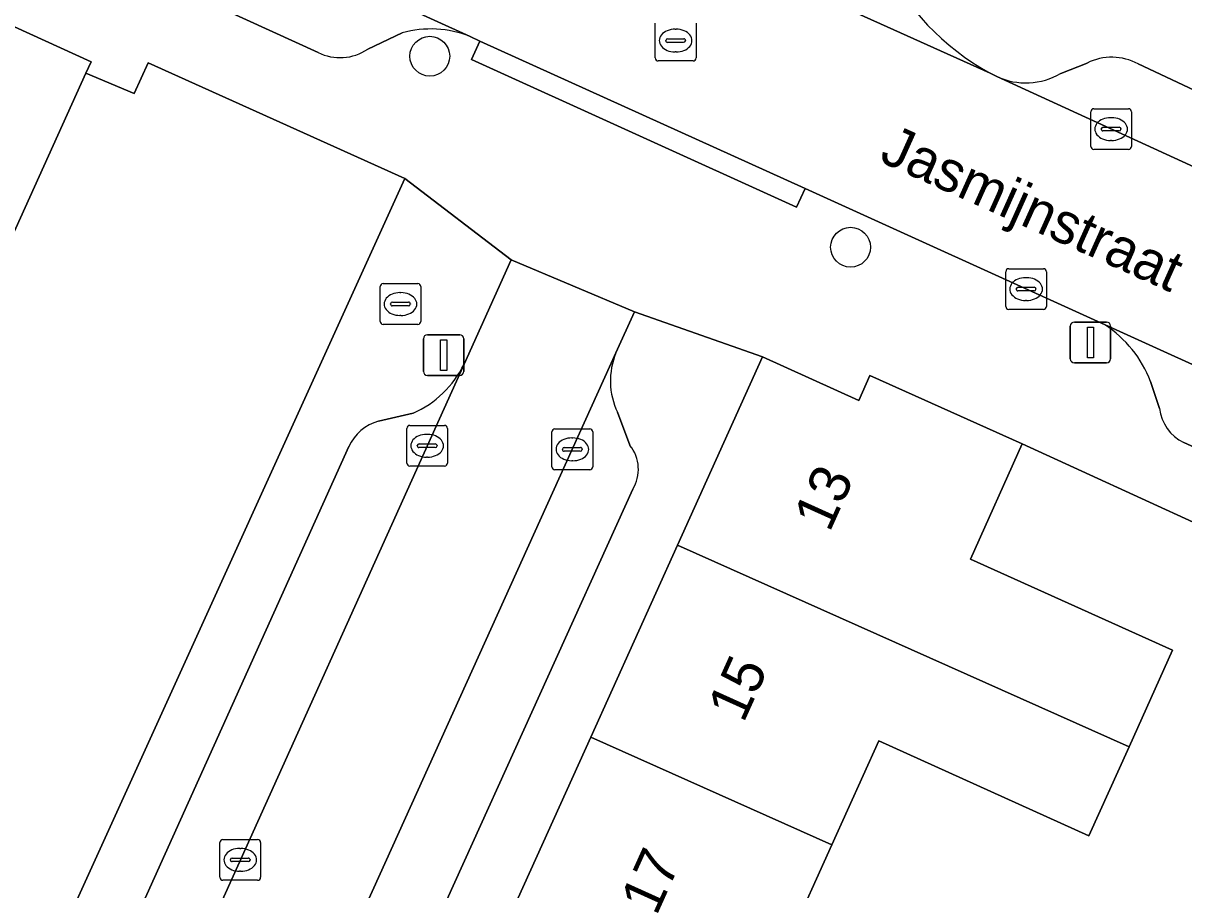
# Model space of a CAD drawing. Extents: x 161838 to 162344, y 381620 to 382160.
# Drawn here: x 162080.38 to 162108.87, y 381769.35 to 381790.62 of the extents above; entities that cross this region are included whole.
import ezdxf

# ---------------------------------------------------------------- set-up
doc = ezdxf.new("R2010")
doc.units = 0
for name, color, linetype in [('IMGEO_Boom', 7, 'Continuous'), ('IMGEO_Brandkraan', 7, 'Continuous'), ('IMGEO_Erf', 7, 'Continuous'), ('IMGEO_Kolk', 7, 'Continuous'), ('IMGEO_Lichtmast', 7, 'Continuous'), ('IMGEO_Muur', 7, 'Continuous'), ('IMGEO_Openbare_ruimte_label', 7, 'Continuous'), ('IMGEO_Pand', 7, 'Continuous'), ('IMGEO_Pand_nummerreeks', 7, 'Continuous'), ('IMGEO_Parkeervlak_open', 7, 'Continuous'), ('IMGEO_Rijbaan_lokaal_open', 7, 'Continuous'), ('IMGEO_Rioolput', 7, 'Continuous'), ('IMGEO_Voetpad_open', 7, 'Continuous')]:
    doc.layers.add(name, color=color, linetype=linetype)

msp = doc.modelspace()

# ---------------------------------------------------------------- linework, layer by layer
at = {"layer": 'IMGEO_Boom'}
for centre in [(162090.359, 381789.808), (162100.687, 381785.121)]:
    msp.add_circle(centre, 0.489, dxfattribs=at)
at = {"layer": 'IMGEO_Brandkraan'}
for p, q in [((162089.138, 381783.301), (162089.138, 381784.153)), ((162089.213, 381784.227), (162090.065, 381784.227)), ((162090.139, 381784.153), (162090.139, 381783.301)), ((162089.626, 381784.007), (162089.651, 381784.007)), ((162089.397, 381783.721), (162089.397, 381783.733)), ((162089.835, 381783.684), (162089.437, 381783.684)), ((162089.44, 381783.77), (162089.838, 381783.77)), ((162089.881, 381783.733), (162089.881, 381783.721)), ((162089.649, 381783.447), (162089.624, 381783.447)), ((162090.065, 381783.227), (162089.213, 381783.227))]:
    msp.add_line(p, q, dxfattribs=at)
for points in [[(162089.138, 381783.301), (162089.138, 381784.153)], [(162089.213, 381784.227), (162090.065, 381784.227)], [(162090.139, 381784.153), (162090.139, 381783.301)], [(162090.065, 381783.227), (162089.213, 381783.227)]]:
    msp.add_lwpolyline(points, dxfattribs=at)
for centre, radius, start, end in [((162089.215, 381784.151), 0.0765, 91.552, 178.448), ((162089.215, 381784.151), 0.0765, 91.552, 178.448), ((162090.063, 381784.151), 0.0765, 1.552, 88.448), ((162090.063, 381784.151), 0.0765, 1.552, 88.448), ((162089.437, 381783.73), 0.0403, 85.8775, 175.7526), ((162089.434, 381783.72), 0.0366, 178.938, 274.7102), ((162089.838, 381783.727), 0.043, 264.8664, 352.4533), ((162089.842, 381783.732), 0.0386, 1.7309, 96.639), ((162089.215, 381783.303), 0.0765, 181.552, 268.448), ((162089.215, 381783.303), 0.0765, 181.552, 268.448), ((162090.063, 381783.303), 0.0765, 271.552, 358.448), ((162090.063, 381783.303), 0.0765, 271.552, 358.448)]:
    msp.add_arc(centre, radius, start, end, dxfattribs=at)
for centre, major_axis, ratio, start_param, end_param in [((162089.625, 381783.727), (-0.387, 0.002), 0.722429, 4.712389, 7.853982), ((162089.65, 381783.727), (-0.39, 0.002), 0.717154, 1.570796, 4.712389)]:
    msp.add_ellipse(centre, major_axis=major_axis, ratio=ratio, start_param=start_param, end_param=end_param, dxfattribs=at)
at = {"layer": 'IMGEO_Erf'}
msp.add_lwpolyline([(162068.579, 381756.936), (162068.219, 381756.057), (162074.49, 381753.282), (162089.747, 381786.804), (162083.445, 381789.649), (162083.105, 381788.89), (162081.916, 381789.39), (162079.965, 381785.079), (162077.918, 381780.552), (162075.797, 381775.863), (162073.603, 381771.013), (162071.478, 381766.316), (162069.301, 381761.504), (162067.446, 381757.401)], close=True, dxfattribs=at)
msp.add_lwpolyline([(162119.551, 381773.591), (162104.902, 381780.293), (162103.63, 381777.467), (162108.591, 381775.234), (162107.525, 381772.865), (162106.539, 381770.675), (162101.379, 381773.006), (162100.229, 381770.46), (162099.172, 381768.121), (162104.172, 381765.858), (162103.149, 381763.595), (162102.061, 381761.187), (162097.027, 381763.433), (162095.939, 381761.023), (162094.867, 381758.649), (162099.869, 381756.389), (162098.796, 381754.013), (162097.756, 381751.711), (162092.728, 381753.983), (162091.62, 381751.529), (162090.929, 381750), (162090.511, 381749.074), (162095.561, 381746.795)], dxfattribs=at)
at = {"layer": 'IMGEO_Kolk'}
for p, q in [((162106.584, 381787.594), (162106.584, 381788.446)), ((162106.659, 381788.52), (162107.511, 381788.52)), ((162107.585, 381788.446), (162107.585, 381787.594)), ((162107.072, 381788.3), (162107.097, 381788.3)), ((162106.843, 381788.014), (162106.843, 381788.026)), ((162107.281, 381787.977), (162106.883, 381787.977)), ((162106.886, 381788.063), (162107.284, 381788.063)), ((162107.327, 381788.026), (162107.327, 381788.014)), ((162107.511, 381787.52), (162106.659, 381787.52)), ((162107.095, 381787.74), (162107.07, 381787.74)), ((162104.497, 381783.668), (162104.497, 381784.52)), ((162104.572, 381784.594), (162105.424, 381784.594)), ((162105.498, 381784.52), (162105.498, 381783.668)), ((162104.756, 381784.088), (162104.756, 381784.1)), ((162104.799, 381784.137), (162105.197, 381784.137)), ((162104.985, 381784.374), (162105.01, 381784.374)), ((162105.24, 381784.1), (162105.24, 381784.088)), ((162105.194, 381784.051), (162104.796, 381784.051)), ((162105.008, 381783.814), (162104.983, 381783.814)), ((162105.424, 381783.594), (162104.572, 381783.594)), ((162089.868, 381780.75), (162090.72, 381780.75)), ((162089.793, 381779.824), (162089.793, 381780.676)), ((162090.281, 381780.53), (162090.306, 381780.53)), ((162090.794, 381780.676), (162090.794, 381779.824)), ((162093.357, 381779.736), (162093.357, 381780.588)), ((162093.432, 381780.662), (162094.284, 381780.662)), ((162093.845, 381780.442), (162093.87, 381780.442)), ((162094.358, 381780.588), (162094.358, 381779.736)), ((162090.052, 381780.244), (162090.052, 381780.256)), ((162090.49, 381780.207), (162090.092, 381780.207)), ((162090.095, 381780.293), (162090.493, 381780.293)), ((162090.536, 381780.256), (162090.536, 381780.244)), ((162093.616, 381780.156), (162093.616, 381780.168)), ((162094.054, 381780.119), (162093.656, 381780.119)), ((162093.659, 381780.205), (162094.057, 381780.205)), ((162094.1, 381780.168), (162094.1, 381780.156)), ((162090.304, 381779.97), (162090.279, 381779.97)), ((162093.868, 381779.882), (162093.843, 381779.882)), ((162090.72, 381779.75), (162089.868, 381779.75)), ((162094.284, 381779.662), (162093.432, 381779.662)), ((162085.204, 381769.662), (162085.204, 381770.514)), ((162085.279, 381770.588), (162086.131, 381770.588)), ((162086.205, 381770.514), (162086.205, 381769.662)), ((162085.692, 381770.368), (162085.717, 381770.368)), ((162085.463, 381770.082), (162085.463, 381770.094)), ((162085.901, 381770.045), (162085.503, 381770.045)), ((162085.506, 381770.131), (162085.904, 381770.131)), ((162085.947, 381770.094), (162085.947, 381770.082)), ((162086.131, 381769.588), (162085.279, 381769.588)), ((162085.715, 381769.808), (162085.69, 381769.808))]:
    msp.add_line(p, q, dxfattribs=at)
for points in [[(162106.584, 381787.594), (162106.584, 381788.446)], [(162106.659, 381788.52), (162107.511, 381788.52)], [(162107.585, 381788.446), (162107.585, 381787.594)], [(162107.511, 381787.52), (162106.659, 381787.52)], [(162104.497, 381783.668), (162104.497, 381784.52)], [(162104.572, 381784.594), (162105.424, 381784.594)], [(162105.498, 381784.52), (162105.498, 381783.668)], [(162105.424, 381783.594), (162104.572, 381783.594)], [(162089.868, 381780.75), (162090.72, 381780.75)], [(162089.793, 381779.824), (162089.793, 381780.676)], [(162090.794, 381780.676), (162090.794, 381779.824)], [(162093.357, 381779.736), (162093.357, 381780.588)], [(162093.432, 381780.662), (162094.284, 381780.662)], [(162094.358, 381780.588), (162094.358, 381779.736)], [(162090.72, 381779.75), (162089.868, 381779.75)], [(162094.284, 381779.662), (162093.432, 381779.662)], [(162085.204, 381769.662), (162085.204, 381770.514)], [(162085.279, 381770.588), (162086.131, 381770.588)], [(162086.205, 381770.514), (162086.205, 381769.662)], [(162086.131, 381769.588), (162085.279, 381769.588)]]:
    msp.add_lwpolyline(points, dxfattribs=at)
for centre, radius, start, end in [((162106.661, 381788.444), 0.0765, 91.552, 178.448), ((162106.661, 381788.444), 0.0765, 91.552, 178.448), ((162107.509, 381788.444), 0.0765, 1.552, 88.448), ((162107.509, 381788.444), 0.0765, 1.552, 88.448), ((162106.883, 381788.023), 0.0403, 85.8775, 175.7526), ((162106.88, 381788.013), 0.0366, 178.938, 274.7102), ((162107.284, 381788.02), 0.043, 264.8664, 352.4533), ((162107.288, 381788.025), 0.0386, 1.7309, 96.639), ((162106.661, 381787.596), 0.0765, 181.552, 268.448), ((162106.661, 381787.596), 0.0765, 181.552, 268.448), ((162107.509, 381787.596), 0.0765, 271.552, 358.448), ((162107.509, 381787.596), 0.0765, 271.552, 358.448), ((162104.574, 381784.518), 0.0765, 91.552, 178.448), ((162104.574, 381784.518), 0.0765, 91.552, 178.448), ((162105.422, 381784.518), 0.0765, 1.552, 88.448), ((162105.422, 381784.518), 0.0765, 1.552, 88.448), ((162104.796, 381784.097), 0.0403, 85.8775, 175.7526), ((162105.201, 381784.099), 0.0386, 1.7309, 96.639), ((162104.793, 381784.087), 0.0366, 178.938, 274.7102), ((162105.197, 381784.094), 0.043, 264.8664, 352.4533), ((162104.574, 381783.67), 0.0765, 181.552, 268.448), ((162104.574, 381783.67), 0.0765, 181.552, 268.448), ((162105.422, 381783.67), 0.0765, 271.552, 358.448), ((162105.422, 381783.67), 0.0765, 271.552, 358.448), ((162089.87, 381780.674), 0.0765, 91.552, 178.448), ((162089.87, 381780.674), 0.0765, 91.552, 178.448), ((162090.718, 381780.674), 0.0765, 1.552, 88.448), ((162090.718, 381780.674), 0.0765, 1.552, 88.448), ((162093.434, 381780.586), 0.0765, 91.552, 178.448), ((162093.434, 381780.586), 0.0765, 91.552, 178.448), ((162094.282, 381780.586), 0.0765, 1.552, 88.448), ((162094.282, 381780.586), 0.0765, 1.552, 88.448), ((162090.092, 381780.253), 0.0403, 85.8775, 175.7526), ((162090.089, 381780.243), 0.0366, 178.938, 274.7102), ((162090.493, 381780.25), 0.043, 264.8664, 352.4533), ((162090.497, 381780.255), 0.0386, 1.7309, 96.639), ((162093.656, 381780.165), 0.0403, 85.8775, 175.7526), ((162093.653, 381780.155), 0.0366, 178.938, 274.7102), ((162094.057, 381780.162), 0.043, 264.8664, 352.4533), ((162094.061, 381780.167), 0.0386, 1.7309, 96.639), ((162089.87, 381779.826), 0.0765, 181.552, 268.448), ((162089.87, 381779.826), 0.0765, 181.552, 268.448), ((162090.718, 381779.826), 0.0765, 271.552, 358.448), ((162090.718, 381779.826), 0.0765, 271.552, 358.448), ((162093.434, 381779.738), 0.0765, 181.552, 268.448), ((162093.434, 381779.738), 0.0765, 181.552, 268.448), ((162094.282, 381779.738), 0.0765, 271.552, 358.448), ((162094.282, 381779.738), 0.0765, 271.552, 358.448), ((162085.281, 381770.512), 0.0765, 91.552, 178.448), ((162085.281, 381770.512), 0.0765, 91.552, 178.448), ((162086.129, 381770.512), 0.0765, 1.552, 88.448), ((162086.129, 381770.512), 0.0765, 1.552, 88.448), ((162085.503, 381770.091), 0.0403, 85.8775, 175.7526), ((162085.5, 381770.081), 0.0366, 178.938, 274.7102), ((162085.904, 381770.088), 0.043, 264.8664, 352.4533), ((162085.908, 381770.093), 0.0386, 1.7309, 96.639), ((162085.281, 381769.664), 0.0765, 181.552, 268.448), ((162085.281, 381769.664), 0.0765, 181.552, 268.448), ((162086.129, 381769.664), 0.0765, 271.552, 358.448), ((162086.129, 381769.664), 0.0765, 271.552, 358.448)]:
    msp.add_arc(centre, radius, start, end, dxfattribs=at)
for centre, major_axis, ratio, start_param, end_param in [((162107.071, 381788.02), (-0.387, 0.002), 0.722429, 4.712389, 7.853982), ((162107.096, 381788.02), (-0.39, 0.002), 0.717154, 1.570796, 4.712389), ((162104.984, 381784.094), (-0.387, 0.002), 0.722429, 4.712389, 7.853982), ((162105.009, 381784.094), (-0.39, 0.002), 0.717154, 1.570796, 4.712389), ((162090.28, 381780.25), (-0.387, 0.002), 0.722429, 4.712389, 7.853982), ((162090.305, 381780.25), (-0.39, 0.002), 0.717154, 1.570796, 4.712389), ((162093.844, 381780.162), (-0.387, 0.002), 0.722429, 4.712389, 7.853982), ((162093.869, 381780.162), (-0.39, 0.002), 0.717154, 1.570796, 4.712389), ((162085.691, 381770.088), (-0.387, 0.002), 0.722429, 4.712389, 7.853982), ((162085.716, 381770.088), (-0.39, 0.002), 0.717154, 1.570796, 4.712389)]:
    msp.add_ellipse(centre, major_axis=major_axis, ratio=ratio, start_param=start_param, end_param=end_param, dxfattribs=at)
at = {"layer": 'IMGEO_Lichtmast'}
for p, q in [((162106.182, 381783.284), (162106.972, 381783.284)), ((162106.972, 381783.284), (162106.182, 381783.284)), ((162090.303, 381782.974), (162091.093, 381782.974)), ((162091.093, 381782.974), (162090.303, 381782.974)), ((162106.082, 381782.384), (162106.082, 381783.184)), ((162106.082, 381783.184), (162106.082, 381782.384)), ((162107.072, 381783.184), (162107.072, 381782.384)), ((162107.072, 381782.384), (162107.072, 381783.184)), ((162090.203, 381782.074), (162090.203, 381782.874)), ((162090.203, 381782.874), (162090.203, 381782.074)), ((162091.193, 381782.874), (162091.193, 381782.074)), ((162091.193, 381782.074), (162091.193, 381782.874)), ((162106.972, 381782.284), (162106.182, 381782.284)), ((162106.182, 381782.284), (162106.972, 381782.284)), ((162091.093, 381781.974), (162090.303, 381781.974)), ((162090.303, 381781.974), (162091.093, 381781.974))]:
    msp.add_line(p, q, dxfattribs=at)
for points in [[(162106.502, 381783.159), (162106.652, 381783.159), (162106.652, 381782.409), (162106.502, 381782.409), (162106.502, 381783.159)], [(162090.623, 381782.849), (162090.773, 381782.849), (162090.773, 381782.099), (162090.623, 381782.099), (162090.623, 381782.849)]]:
    msp.add_lwpolyline(points, dxfattribs=at)
for centre, start, end in [((162106.182, 381783.184), 90, 180), ((162106.182, 381783.184), 90, 180), ((162106.972, 381783.184), 0, 90), ((162106.972, 381783.184), 360, 90), ((162090.303, 381782.874), 90, 180), ((162090.303, 381782.874), 90, 180), ((162091.093, 381782.874), 0, 90), ((162091.093, 381782.874), 360, 90), ((162106.182, 381782.384), 180, 270), ((162106.182, 381782.384), 180, 270), ((162106.972, 381782.384), 270, 0), ((162106.972, 381782.384), 270, 0), ((162090.303, 381782.074), 180, 270), ((162090.303, 381782.074), 180, 270), ((162091.093, 381782.074), 270, 0), ((162091.093, 381782.074), 270, 0)]:
    msp.add_arc(centre, 0.1, start, end, dxfattribs=at)
at = {"layer": 'IMGEO_Muur'}
msp.add_lwpolyline([(162104.902, 381780.293), (162119.551, 381773.591)], dxfattribs=at)
at = {"layer": 'IMGEO_Pand'}
for points in [[(162073.969, 381787.795), (162079.965, 381785.079), (162081.916, 381789.39), (162082.043, 381789.672), (162079.775, 381790.698), (162080.088, 381791.39), (162071.424, 381795.171), (162070.431, 381792.976), (162075.316, 381790.766)], [(162107.525, 381772.865), (162108.591, 381775.234), (162103.63, 381777.467), (162104.902, 381780.293), (162101.163, 381781.976), (162100.887, 381781.363), (162098.526, 381782.429), (162096.439, 381777.811)], [(162107.525, 381772.865), (162096.439, 381777.811), (162094.311, 381773.1), (162100.229, 381770.46), (162101.379, 381773.006), (162106.539, 381770.675)], [(162100.229, 381770.46), (162094.311, 381773.1), (162092.219, 381768.471), (162103.149, 381763.595), (162104.172, 381765.858), (162099.172, 381768.121)]]:
    msp.add_lwpolyline(points, close=True, dxfattribs=at)
at = {"layer": 'IMGEO_Parkeervlak_open'}
for points in [[(162091.347, 381790.291), (162072.256, 381798.955)], [(162074.274, 381795.987), (162087.616, 381789.9)], [(162088.834, 381789.981), (162089.683, 381790.379)], [(162106.493, 381789.639), (162105.846, 381789.382)], [(162121.232, 381783.278), (162107.749, 381789.619)], [(162104.279, 381789.306), (162122.866, 381780.786)], [(162121.187, 381776.749), (162106.934, 381783.216)], [(162094.929, 381782.528), (162080.868, 381751.463), (162080.79, 381751.291)], [(162077.753, 381752.48), (162077.885, 381752.773), (162091.2, 381782.254)], [(162108.049, 381781.825), (162108.268, 381781.166)], [(162089.951, 381781.049), (162089.101, 381780.855)], [(162095.273, 381780.26), (162094.965, 381781.071)], [(162088.368, 381780.23), (162077.427, 381756)], [(162108.868, 381780.331), (162117.733, 381776.281)], [(162083.457, 381752.979), (162085.708, 381757.978), (162084.665, 381758.456), (162085.08, 381759.486), (162086.211, 381759.034), (162095.341, 381779.181)]]:
    msp.add_lwpolyline(points, dxfattribs=at)
for centre, radius, start, end in [((162090.385, 381787.877), 2.599, 68.2733, 105.6722), ((162088.156, 381790.978), 1.206, 243.3981, 304.2114), ((162107.102, 381788.408), 1.374, 61.8767, 116.2988), ((162104.988, 381790.873), 1.72, 245.6503, 299.9031), ((162105.379, 381780.827), 2.85, 20.4894, 56.9406), ((162096.582, 381781.84), 1.79, 157.3937, 205.4371), ((162088.925, 381783.362), 2.53, 293.914, 334.0316), ((162109.327, 381781.294), 1.066, 186.8751, 244.5241), ((162089.438, 381779.717), 1.187, 106.5113, 154.3945), ((162094.541, 381779.672), 0.938, 328.4363, 38.7758)]:
    msp.add_arc(centre, radius, start, end, dxfattribs=at)
at = {"layer": 'IMGEO_Rijbaan_lokaal_open'}
for points in [[(162090.301, 381795.665), (162088.104, 381796.655), (162074.133, 381802.954), (162072.873, 381803.522), (162071.777, 381801.203), (162070.987, 381799.531), (162072.256, 381798.955), (162091.347, 381790.291), (162091.591, 381790.18), (162099.57, 381786.559), (162106.934, 381783.216), (162121.187, 381776.749), (162122.089, 381776.34), (162123.078, 381778.527), (162123.887, 381780.318), (162122.866, 381780.786), (162104.279, 381789.306), (162104.113, 381789.392), (162091.158, 381795.22)], [(162094.929, 381782.528), (162095.383, 381783.532), (162092.357, 381784.815), (162091.2, 381782.254), (162077.885, 381752.773), (162080.868, 381751.463)]]:
    msp.add_lwpolyline(points, close=True, dxfattribs=at)
msp.add_lwpolyline([(162090.301, 381795.665), (162091.158, 381795.22), (162104.113, 381789.392)], dxfattribs=at)
msp.add_arc((162107.129, 381794.886), 6.268, 170.9532, 241.2394, dxfattribs=at)
at = {"layer": 'IMGEO_Rioolput'}
for p, q in [((162095.893, 381789.765), (162095.893, 381790.617)), ((162096.381, 381790.471), (162096.406, 381790.471)), ((162096.894, 381790.617), (162096.894, 381789.765)), ((162096.152, 381790.185), (162096.152, 381790.197)), ((162096.59, 381790.148), (162096.192, 381790.148)), ((162096.195, 381790.234), (162096.593, 381790.234)), ((162096.636, 381790.197), (162096.636, 381790.185)), ((162096.404, 381789.911), (162096.379, 381789.911)), ((162096.82, 381789.691), (162095.968, 381789.691))]:
    msp.add_line(p, q, dxfattribs=at)
for points in [[(162095.893, 381789.765), (162095.893, 381790.617)], [(162096.894, 381790.617), (162096.894, 381789.765)], [(162096.82, 381789.691), (162095.968, 381789.691)]]:
    msp.add_lwpolyline(points, dxfattribs=at)
for centre, radius, start, end in [((162096.192, 381790.194), 0.0403, 85.8775, 175.7526), ((162096.189, 381790.184), 0.0366, 178.938, 274.7102), ((162096.593, 381790.191), 0.043, 264.8664, 352.4533), ((162096.597, 381790.196), 0.0386, 1.7309, 96.639), ((162095.97, 381789.767), 0.0765, 181.552, 268.448), ((162095.97, 381789.767), 0.0765, 181.552, 268.448), ((162096.818, 381789.767), 0.0765, 271.552, 358.448), ((162096.818, 381789.767), 0.0765, 271.552, 358.448)]:
    msp.add_arc(centre, radius, start, end, dxfattribs=at)
for centre, major_axis, ratio, start_param, end_param in [((162096.38, 381790.191), (-0.387, 0.002), 0.722429, 4.712389, 7.853982), ((162096.405, 381790.191), (-0.39, 0.002), 0.717154, 1.570796, 4.712389)]:
    msp.add_ellipse(centre, major_axis=major_axis, ratio=ratio, start_param=start_param, end_param=end_param, dxfattribs=at)
at = {"layer": 'IMGEO_Voetpad_open'}
for points in [[(162064.04, 381798.645), (162065.308, 381798.05), (162071.424, 381795.171), (162080.088, 381791.39), (162079.775, 381790.698), (162082.043, 381789.672), (162081.916, 381789.39), (162083.105, 381788.89), (162083.445, 381789.649), (162089.747, 381786.804), (162092.357, 381784.815), (162095.383, 381783.532), (162098.526, 381782.429), (162100.887, 381781.363), (162101.163, 381781.976), (162104.902, 381780.293), (162119.551, 381773.591)], [(162087.616, 381789.9), (162074.274, 381795.987)], [(162089.683, 381790.379), (162088.834, 381789.981)], [(162106.934, 381783.216), (162099.57, 381786.559), (162099.362, 381786.105), (162091.383, 381789.727), (162091.591, 381790.18), (162091.347, 381790.291)], [(162105.846, 381789.382), (162106.493, 381789.639)], [(162107.749, 381789.619), (162121.232, 381783.278)], [(162104.113, 381789.392), (162104.279, 381789.306)], [(162092.357, 381784.815), (162089.747, 381786.804), (162074.49, 381753.282), (162077.753, 381752.48)], [(162091.2, 381782.254), (162092.357, 381784.815)], [(162098.526, 381782.429), (162095.383, 381783.532), (162094.929, 381782.528)], [(162080.79, 381751.291), (162083.788, 381749.81), (162083.874, 381750), (162085.748, 381754.149), (162087.886, 381758.88), (162090.043, 381763.653), (162092.219, 381768.471), (162094.311, 381773.1), (162096.439, 381777.811), (162098.526, 381782.429)], [(162108.268, 381781.166), (162108.049, 381781.825)], [(162089.101, 381780.855), (162089.951, 381781.049)], [(162094.965, 381781.071), (162095.273, 381780.26)], [(162077.427, 381756), (162088.368, 381780.23)], [(162117.733, 381776.281), (162108.868, 381780.331)], [(162095.341, 381779.181), (162086.211, 381759.034), (162085.08, 381759.486), (162084.665, 381758.456), (162085.708, 381757.978), (162083.457, 381752.979)]]:
    msp.add_lwpolyline(points, dxfattribs=at)
msp.add_lwpolyline([(162091.591, 381790.18), (162091.383, 381789.727), (162099.362, 381786.105), (162099.57, 381786.559)], close=True, dxfattribs=at)
for centre, radius, start, end in [((162107.129, 381794.886), 6.268, 170.9532, 241.2394), ((162090.385, 381787.877), 2.599, 68.2733, 105.6722), ((162088.156, 381790.978), 1.206, 243.3981, 304.2114), ((162107.102, 381788.408), 1.374, 61.8767, 116.2988), ((162104.988, 381790.873), 1.72, 245.6503, 299.9031), ((162105.379, 381780.827), 2.85, 20.4894, 56.9406), ((162096.582, 381781.84), 1.79, 157.3937, 205.4371), ((162088.925, 381783.362), 2.53, 293.914, 334.0316), ((162109.327, 381781.294), 1.066, 186.8751, 244.5241), ((162089.438, 381779.717), 1.187, 106.5113, 154.3945), ((162094.541, 381779.672), 0.938, 328.4363, 38.7758)]:
    msp.add_arc(centre, radius, start, end, dxfattribs=at)

# ---------------------------------------------------------------- texts
at = {"layer": 'IMGEO_Openbare_ruimte_label'}
msp.add_text('Jasmijnstraat', height=1, rotation=335.7932, dxfattribs=at).set_placement((162101.36, 381787.241))
at = {"layer": 'IMGEO_Pand_nummerreeks'}
for s, rotation, p in [('13', 65.6857, (162100.169, 381778.1)), ('15', 65.6857, (162098.057, 381773.425)), ('17', 65.6839, (162095.919, 381768.692))]:
    msp.add_text(s, height=1, rotation=rotation, dxfattribs=at).set_placement(p)

doc.saveas('drawing.dxf')
